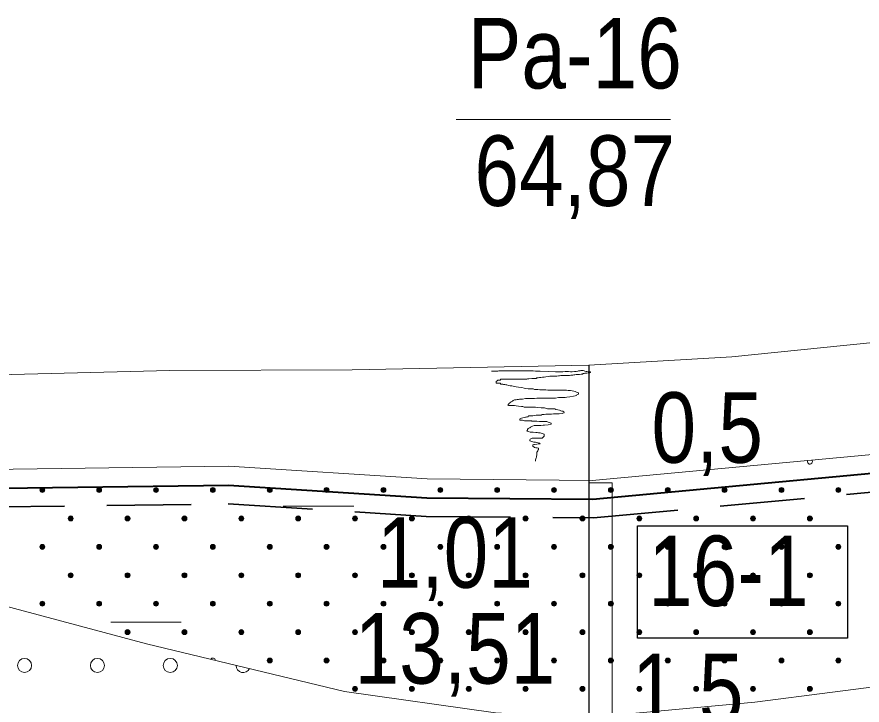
# Model space of a CAD drawing. Extents: x 640121 to 640955, y 6441885 to 6442246.
# Drawn here: x 640850.27 to 640886.22, y 6442146.39 to 6442175.68 of the extents above; entities that cross this region are included whole.
import ezdxf
from ezdxf.enums import TextEntityAlignment as Align

# ---------------------------------------------------------------- set-up
doc = ezdxf.new("R2010")
doc.units = 0
doc.header["$LTSCALE"] = 1.2
doc.linetypes.add('MEDIUM_DASHED', pattern=[4.5, 3, -1.5])
for name, color, linetype, lineweight in [('31', 7, 'Continuous', 13), ('32', 7, 'Continuous', 13), ('33', 7, 'Continuous', 13), ('35', 7, 'Continuous', 35), ('40', 7, 'Continuous', 13), ('43', 7, 'Continuous', 13), ('45', 7, 'Continuous', 13), ('47', 7, 'Continuous', 13)]:
    doc.layers.add(name, color=color, linetype=linetype, lineweight=lineweight)

msp = doc.modelspace()

# ---------------------------------------------------------------- hatches: boundary and pattern name
at = {"layer": '45'}
for points in [[(640851.424, 6442155.622, 1), (640851.275, 6442155.473, 1)], [(640853.842, 6442155.622, 1), (640853.694, 6442155.473, 1)], [(640856.26, 6442155.622, 1), (640856.112, 6442155.473, 1)], [(640858.679, 6442155.622, 1), (640858.53, 6442155.473, 1)], [(640861.097, 6442155.622, 1), (640860.949, 6442155.473, 1)], [(640863.515, 6442155.622, 1), (640863.367, 6442155.473, 1)], [(640865.934, 6442155.622, 1), (640865.785, 6442155.473, 1)], [(640868.352, 6442155.622, 1), (640868.203, 6442155.473, 1)], [(640870.77, 6442155.622, 1), (640870.622, 6442155.473, 1)], [(640873.189, 6442155.622, 1), (640873.04, 6442155.473, 1)], [(640875.607, 6442155.622, 1), (640875.458, 6442155.473, 1)], [(640878.025, 6442155.622, 1), (640877.877, 6442155.473, 1)], [(640880.443, 6442155.622, 1), (640880.295, 6442155.473, 1)], [(640882.862, 6442155.622, 1), (640882.713, 6442155.473, 1)], [(640885.28, 6442155.622, 1), (640885.132, 6442155.473, 1)], [(640852.633, 6442154.413, 1), (640852.484, 6442154.264, 1)], [(640855.051, 6442154.413, 1), (640854.903, 6442154.264, 1)], [(640857.47, 6442154.413, 1), (640857.321, 6442154.264, 1)], [(640859.888, 6442154.413, 1), (640859.739, 6442154.264, 1)], [(640862.306, 6442154.413, 1), (640862.158, 6442154.264, 1)], [(640864.724, 6442154.413, 1), (640864.576, 6442154.264, 1)], [(640867.143, 6442154.413, 1), (640866.994, 6442154.264, 1)], [(640869.561, 6442154.413, 1), (640869.413, 6442154.264, 1)], [(640871.979, 6442154.413, 1), (640871.831, 6442154.264, 1)], [(640874.398, 6442154.413, 1), (640874.249, 6442154.264, 1)], [(640876.816, 6442154.413, 1), (640876.667, 6442154.264, 1)], [(640879.234, 6442154.413, 1), (640879.086, 6442154.264, 1)], [(640881.653, 6442154.413, 1), (640881.504, 6442154.264, 1)], [(640884.071, 6442154.413, 1), (640883.922, 6442154.264, 1)], [(640851.424, 6442153.204, 1), (640851.275, 6442153.055, 1)], [(640853.842, 6442153.204, 1), (640853.694, 6442153.055, 1)], [(640856.26, 6442153.204, 1), (640856.112, 6442153.055, 1)], [(640858.679, 6442153.204, 1), (640858.53, 6442153.055, 1)], [(640861.097, 6442153.204, 1), (640860.949, 6442153.055, 1)], [(640863.515, 6442153.204, 1), (640863.367, 6442153.055, 1)], [(640865.934, 6442153.204, 1), (640865.785, 6442153.055, 1)], [(640868.352, 6442153.204, 1), (640868.203, 6442153.055, 1)], [(640870.77, 6442153.204, 1), (640870.622, 6442153.055, 1)], [(640873.189, 6442153.204, 1), (640873.04, 6442153.055, 1)], [(640875.607, 6442153.204, 1), (640875.458, 6442153.055, 1)], [(640878.025, 6442153.204, 1), (640877.877, 6442153.055, 1)], [(640880.443, 6442153.204, 1), (640880.295, 6442153.055, 1)], [(640882.862, 6442153.204, 1), (640882.713, 6442153.055, 1)], [(640885.28, 6442153.204, 1), (640885.132, 6442153.055, 1)], [(640852.633, 6442151.994, 1), (640852.484, 6442151.846, 1)], [(640855.051, 6442151.994, 1), (640854.903, 6442151.846, 1)], [(640857.47, 6442151.994, 1), (640857.321, 6442151.846, 1)], [(640859.888, 6442151.994, 1), (640859.739, 6442151.846, 1)], [(640862.306, 6442151.994, 1), (640862.158, 6442151.846, 1)], [(640864.724, 6442151.994, 1), (640864.576, 6442151.846, 1)], [(640867.143, 6442151.994, 1), (640866.994, 6442151.846, 1)], [(640869.561, 6442151.994, 1), (640869.413, 6442151.846, 1)], [(640871.979, 6442151.994, 1), (640871.831, 6442151.846, 1)], [(640874.398, 6442151.994, 1), (640874.249, 6442151.846, 1)], [(640876.816, 6442151.994, 1), (640876.667, 6442151.846, 1)], [(640879.234, 6442151.994, 1), (640879.086, 6442151.846, 1)], [(640881.653, 6442151.994, 1), (640881.504, 6442151.846, 1)], [(640884.071, 6442151.994, 1), (640883.922, 6442151.846, 1)], [(640851.424, 6442150.785, 1), (640851.275, 6442150.637, 1)], [(640853.842, 6442150.785, 1), (640853.694, 6442150.637, 1)], [(640856.26, 6442150.785, 1), (640856.112, 6442150.637, 1)], [(640858.679, 6442150.785, 1), (640858.53, 6442150.637, 1)], [(640861.097, 6442150.785, 1), (640860.949, 6442150.637, 1)], [(640863.515, 6442150.785, 1), (640863.367, 6442150.637, 1)], [(640865.934, 6442150.785, 1), (640865.785, 6442150.637, 1)], [(640868.352, 6442150.785, 1), (640868.203, 6442150.637, 1)], [(640870.77, 6442150.785, 1), (640870.622, 6442150.637, 1)], [(640873.189, 6442150.785, 1), (640873.04, 6442150.637, 1)], [(640875.607, 6442150.785, 1), (640875.458, 6442150.637, 1)], [(640878.025, 6442150.785, 1), (640877.877, 6442150.637, 1)], [(640880.443, 6442150.785, 1), (640880.295, 6442150.637, 1)], [(640882.862, 6442150.785, 1), (640882.713, 6442150.637, 1)], [(640885.28, 6442150.785, 1), (640885.132, 6442150.637, 1)], [(640855.051, 6442149.576, 1), (640854.903, 6442149.428, 1)], [(640857.47, 6442149.576, 1), (640857.321, 6442149.428, 1)], [(640859.888, 6442149.576, 1), (640859.739, 6442149.428, 1)], [(640862.306, 6442149.576, 1), (640862.158, 6442149.428, 1)], [(640864.724, 6442149.576, 1), (640864.576, 6442149.428, 1)], [(640867.143, 6442149.576, 1), (640866.994, 6442149.428, 1)], [(640869.561, 6442149.576, 1), (640869.413, 6442149.428, 1)], [(640871.979, 6442149.576, 1), (640871.831, 6442149.428, 1)], [(640874.398, 6442149.576, 1), (640874.249, 6442149.428, 1)], [(640876.816, 6442149.576, 1), (640876.667, 6442149.428, 1)], [(640879.234, 6442149.576, 1), (640879.086, 6442149.428, 1)], [(640881.653, 6442149.576, 1), (640881.504, 6442149.428, 1)], [(640884.071, 6442149.576, 1), (640883.922, 6442149.428, 1)], [(640861.097, 6442148.367, 1), (640860.949, 6442148.219, 1)], [(640863.515, 6442148.367, 1), (640863.367, 6442148.219, 1)], [(640865.934, 6442148.367, 1), (640865.785, 6442148.219, 1)], [(640868.352, 6442148.367, 1), (640868.203, 6442148.219, 1)], [(640870.77, 6442148.367, 1), (640870.622, 6442148.219, 1)], [(640873.189, 6442148.367, 1), (640873.04, 6442148.219, 1)], [(640875.607, 6442148.367, 1), (640875.458, 6442148.219, 1)], [(640878.025, 6442148.367, 1), (640877.877, 6442148.219, 1)], [(640880.443, 6442148.367, 1), (640880.295, 6442148.219, 1)], [(640882.862, 6442148.367, 1), (640882.713, 6442148.219, 1)], [(640885.28, 6442148.367, 1), (640885.132, 6442148.219, 1)], [(640864.724, 6442147.158, 1), (640864.576, 6442147.009, 1)], [(640867.143, 6442147.158, 1), (640866.994, 6442147.009, 1)], [(640869.561, 6442147.158, 1), (640869.413, 6442147.009, 1)], [(640871.979, 6442147.158, 1), (640871.831, 6442147.009, 1)], [(640874.398, 6442147.158, 1), (640874.249, 6442147.009, 1)], [(640876.816, 6442147.158, 1), (640876.667, 6442147.009, 1)], [(640879.234, 6442147.158, 1), (640879.086, 6442147.009, 1)], [(640881.653, 6442147.158, 1), (640881.504, 6442147.009, 1)], [(640884.071, 6442147.158, 1), (640883.922, 6442147.009, 1)]]:
    msp.add_hatch(color=256, dxfattribs=at).paths.add_polyline_path(points)

# ---------------------------------------------------------------- linework, layer by layer
at = {"layer": '31'}
for points in [[(640766.27, 6442166.81), (640772.42, 6442164.18), (640775.97, 6442162.88), (640778.51, 6442161.86), (640779.92, 6442161.1), (640782.4, 6442159.37), (640784.73, 6442157.26), (640785.79, 6442156.66), (640789.05, 6442156.34), (640792.15, 6442156.48), (640797.43, 6442156.68), (640805.3, 6442157.27), (640819.95, 6442158.83), (640830.66, 6442159.34), (640843.85, 6442160.31), (640856.77, 6442160.63), (640864.53, 6442160.67), (640874.59, 6442160.86), (640880.68, 6442161.21), (640890.6, 6442162.23)], [(640771.49, 6442163.12), (640774.28, 6442161.82), (640776.71, 6442160.81), (640779.36, 6442159.25), (640784.92, 6442155.11), (640785.41, 6442154.87), (640785.78, 6442154.67), (640787.15, 6442154.55), (640789.13, 6442154.57), (640793.8, 6442154.85), (640797.19, 6442155.11), (640800.45, 6442155.32), (640807.52, 6442155.7), (640815.1, 6442156.02), (640823.55, 6442156.02), (640837.86, 6442156.27), (640859.29, 6442156.56), (640867.72, 6442156.02), (640874.73, 6442155.96), (640892.32, 6442157.59), (640908.53, 6442160.16), (640920.53, 6442162.05), (640928.43, 6442163.08), (640933.07, 6442163.64)], [(640827.29, 6442156.09), (640846.55, 6442151.47), (640855.78, 6442149), (640864.21, 6442146.97), (640870.63, 6442146.07), (640874.45, 6442145.85), (640881.65, 6442146.52), (640888.26, 6442147.37), (640905.62, 6442150.12), (640920.7, 6442152.04), (640935.32, 6442154.62)]]:
    msp.add_lwpolyline(points, dxfattribs=at)
at = {"layer": '32'}
msp.add_line((640868.95, 6442171.32), (640878.07, 6442171.32), dxfattribs=at)
at = {"layer": '32', "lineweight": 25}
msp.add_line((640874.59, 6442160.86), (640874.59, 6442115.86), dxfattribs=at)
at = {"layer": '33'}
msp.add_lwpolyline([(640875.59, 6442145.96), (640875.59, 6442155.86), (640874.73, 6442155.86), (640874.59, 6442155.86), (640874.59, 6442145.86), (640874.63, 6442145.86)], close=True, dxfattribs=at)
at = {"layer": '33', "lineweight": 25}
msp.add_lwpolyline([(640876.67, 6442154.03), (640885.59, 6442154.03), (640885.59, 6442149.25), (640876.67, 6442149.25)], close=True, dxfattribs=at)
at = {"layer": '35', "lineweight": 40}
msp.add_lwpolyline([(640771.15, 6442162.4), (640773.96, 6442161.09), (640776.35, 6442160.1), (640778.91, 6442158.58), (640784.51, 6442154.42), (640785.04, 6442154.16), (640785.54, 6442153.88), (640787.12, 6442153.75), (640789.16, 6442153.77), (640793.85, 6442154.05), (640797.24, 6442154.31), (640800.5, 6442154.52), (640807.56, 6442154.9), (640815.12, 6442155.22), (640823.56, 6442155.22), (640837.88, 6442155.47), (640859.27, 6442155.76), (640867.7, 6442155.22), (640874.77, 6442155.16), (640892.41, 6442156.8), (640908.65, 6442159.37), (640919.89, 6442161.14)], dxfattribs=at)
at = {"layer": '35', "linetype": 'MEDIUM_DASHED'}
msp.add_lwpolyline([(640770.82, 6442161.67), (640773.64, 6442160.36), (640775.99, 6442159.38), (640778.47, 6442157.91), (640784.09, 6442153.73), (640784.67, 6442153.45), (640785.3, 6442153.1), (640787.09, 6442152.95), (640789.18, 6442152.97), (640793.9, 6442153.25), (640797.3, 6442153.51), (640800.54, 6442153.72), (640807.6, 6442154.1), (640815.14, 6442154.42), (640823.57, 6442154.42), (640837.89, 6442154.67), (640859.25, 6442154.96), (640867.67, 6442154.42), (640874.8, 6442154.36), (640892.51, 6442156), (640908.78, 6442158.58), (640919.09, 6442160.21)], dxfattribs=at)
at = {"layer": '40'}
for points in [[(640870.46, 6442160.6), (640870.52, 6442160.6), (640870.63, 6442160.6), (640870.73, 6442160.6), (640870.76, 6442160.62), (640870.87, 6442160.62), (640871.02, 6442160.62), (640871.35, 6442160.62), (640871.53, 6442160.62), (640871.56, 6442160.62), (640871.6, 6442160.62), (640871.67, 6442160.62), (640871.75, 6442160.62), (640871.86, 6442160.62), (640871.95, 6442160.62), (640872.01, 6442160.62), (640872.09, 6442160.62), (640872.16, 6442160.62), (640872.23, 6442160.62), (640872.32, 6442160.6), (640872.37, 6442160.6), (640872.44, 6442160.6), (640872.53, 6442160.6), (640872.87, 6442160.59), (640873.18, 6442160.58), (640873.28, 6442160.58), (640873.34, 6442160.58), (640873.37, 6442160.58), (640873.42, 6442160.58), (640873.49, 6442160.58), (640873.59, 6442160.59), (640873.64, 6442160.59), (640873.67, 6442160.59), (640873.7, 6442160.59), (640873.73, 6442160.59), (640873.81, 6442160.58), (640873.84, 6442160.58), (640873.89, 6442160.58), (640873.99, 6442160.59), (640874.05, 6442160.59), (640874.12, 6442160.6), (640874.15, 6442160.62), (640874.23, 6442160.62), (640874.26, 6442160.63), (640874.31, 6442160.63), (640874.36, 6442160.63), (640874.39, 6442160.62), (640874.43, 6442160.6), (640874.48, 6442160.59), (640874.51, 6442160.59)], [(640871.99, 6442160.28), (640871.96, 6442160.27), (640871.9, 6442160.27), (640871.86, 6442160.26), (640871.83, 6442160.26), (640871.79, 6442160.26), (640871.74, 6442160.26), (640871.69, 6442160.26), (640871.65, 6442160.26), (640871.57, 6442160.26), (640871.54, 6442160.26), (640871.48, 6442160.27), (640871.44, 6442160.27), (640871.41, 6442160.27), (640871.37, 6442160.27), (640871.32, 6442160.27), (640871.27, 6442160.27), (640871.2, 6442160.27), (640871.17, 6442160.27), (640871.13, 6442160.27), (640871.07, 6442160.27), (640871.03, 6442160.27), (640870.99, 6442160.27), (640870.95, 6442160.27), (640870.9, 6442160.27), (640870.85, 6442160.26), (640870.82, 6442160.23), (640870.77, 6442160.23), (640870.73, 6442160.22), (640870.71, 6442160.21), (640870.69, 6442160.2), (640870.66, 6442160.17), (640870.65, 6442160.14), (640870.66, 6442160.1), (640870.76, 6442160.09), (640870.82, 6442160.09), (640870.85, 6442160.06), (640870.9, 6442160.06), (640870.94, 6442160.05), (640870.96, 6442160.04), (640871.02, 6442160.04), (640871.07, 6442160.03), (640871.11, 6442160.02), (640871.18, 6442159.99), (640871.25, 6442159.98), (640871.32, 6442159.98), (640871.37, 6442159.97), (640871.42, 6442159.96), (640871.5, 6442159.94), (640871.61, 6442159.93)], [(640874.51, 6442160.59), (640874.56, 6442160.58), (640874.6, 6442160.58), (640874.65, 6442160.58), (640874.67, 6442160.56), (640874.65, 6442160.54), (640874.66, 6442160.56), (640874.62, 6442160.54), (640874.57, 6442160.53), (640874.51, 6442160.52), (640874.48, 6442160.52), (640874.43, 6442160.52), (640874.39, 6442160.51), (640874.36, 6442160.51), (640874.33, 6442160.48), (640874.27, 6442160.48), (640874.2, 6442160.47), (640874.17, 6442160.47), (640874.05, 6442160.46), (640874, 6442160.45), (640873.96, 6442160.45), (640873.91, 6442160.44), (640873.87, 6442160.44), (640873.83, 6442160.44), (640873.77, 6442160.42), (640873.73, 6442160.42), (640873.63, 6442160.42), (640873.57, 6442160.42), (640873.49, 6442160.42), (640873.41, 6442160.42), (640873.35, 6442160.41), (640873.3, 6442160.41), (640873.24, 6442160.4), (640873.18, 6442160.4), (640873.01, 6442160.4), (640872.98, 6442160.4), (640872.94, 6442160.39), (640872.87, 6442160.38), (640872.77, 6442160.36), (640872.69, 6442160.35), (640872.63, 6442160.35), (640872.55, 6442160.34), (640872.49, 6442160.34), (640872.44, 6442160.32), (640872.38, 6442160.32), (640872.35, 6442160.3), (640872.32, 6442160.3), (640872.26, 6442160.3), (640872.21, 6442160.29), (640872.17, 6442160.29), (640872.04, 6442160.28), (640871.99, 6442160.28)], [(640871.61, 6442159.93), (640871.75, 6442159.91), (640871.85, 6442159.88), (640871.91, 6442159.87), (640872.01, 6442159.86), (640872.1, 6442159.86), (640872.17, 6442159.85), (640872.23, 6442159.85), (640872.28, 6442159.82), (640872.37, 6442159.82), (640872.43, 6442159.82), (640872.51, 6442159.81), (640872.59, 6442159.81), (640872.67, 6442159.81), (640872.76, 6442159.81), (640872.85, 6442159.8), (640872.91, 6442159.8), (640872.94, 6442159.8), (640873.01, 6442159.8), (640873.09, 6442159.8), (640873.17, 6442159.8), (640873.27, 6442159.8), (640873.35, 6442159.8), (640873.41, 6442159.8), (640873.49, 6442159.8), (640873.53, 6442159.8), (640873.59, 6442159.8), (640873.65, 6442159.8), (640873.71, 6442159.79), (640873.77, 6442159.79), (640873.82, 6442159.78), (640873.95, 6442159.76), (640874.01, 6442159.74), (640874.07, 6442159.72), (640874.12, 6442159.7), (640874.15, 6442159.69), (640874.15, 6442159.66), (640874.14, 6442159.62), (640874.12, 6442159.61), (640874.09, 6442159.6), (640874.07, 6442159.57), (640874.02, 6442159.56), (640873.94, 6442159.54), (640873.79, 6442159.52), (640873.66, 6442159.5), (640873.59, 6442159.49), (640873.49, 6442159.49), (640873.41, 6442159.48), (640873.31, 6442159.48), (640873.18, 6442159.46), (640872.99, 6442159.46), (640872.82, 6442159.46)], [(640872.82, 6442159.46), (640872.74, 6442159.46), (640872.67, 6442159.46), (640872.58, 6442159.46), (640872.52, 6442159.46), (640872.46, 6442159.46), (640872.38, 6442159.46), (640872.29, 6442159.45), (640872.11, 6442159.45), (640872.03, 6442159.45), (640871.98, 6442159.44), (640871.9, 6442159.44), (640871.78, 6442159.42), (640871.65, 6442159.42), (640871.6, 6442159.4), (640871.54, 6442159.4), (640871.51, 6442159.39), (640871.48, 6442159.38), (640871.44, 6442159.38), (640871.41, 6442159.37), (640871.37, 6442159.36), (640871.35, 6442159.33), (640871.29, 6442159.3), (640871.25, 6442159.27), (640871.24, 6442159.25), (640871.2, 6442159.24), (640871.19, 6442159.21), (640871.17, 6442159.19), (640871.15, 6442159.16), (640871.18, 6442159.15), (640871.21, 6442159.15), (640871.27, 6442159.15), (640871.32, 6442159.15), (640871.43, 6442159.14), (640871.51, 6442159.13), (640871.61, 6442159.12), (640871.73, 6442159.1), (640871.79, 6442159.1), (640871.85, 6442159.08), (640871.91, 6442159.08), (640872.08, 6442159.08), (640872.21, 6442159.08), (640872.32, 6442159.07), (640872.43, 6442159.06), (640872.57, 6442159.04), (640872.71, 6442159.04), (640872.83, 6442159.01), (640872.92, 6442159.01), (640873.01, 6442159.01), (640873.1, 6442159)], [(640873.1, 6442159), (640873.15, 6442159), (640873.19, 6442158.98), (640873.28, 6442158.96), (640873.35, 6442158.95), (640873.4, 6442158.92), (640873.45, 6442158.91), (640873.51, 6442158.9), (640873.53, 6442158.89), (640873.54, 6442158.84), (640873.52, 6442158.83), (640873.49, 6442158.82), (640873.46, 6442158.8), (640873.34, 6442158.79), (640873.28, 6442158.79), (640873.24, 6442158.79), (640873.17, 6442158.79), (640873.09, 6442158.79), (640873, 6442158.78), (640872.95, 6442158.78), (640872.91, 6442158.78), (640872.77, 6442158.78), (640872.7, 6442158.76), (640872.67, 6442158.76), (640872.61, 6442158.76), (640872.57, 6442158.74), (640872.51, 6442158.74), (640872.43, 6442158.74), (640872.35, 6442158.73), (640872.27, 6442158.72), (640872.21, 6442158.71), (640872.17, 6442158.71), (640872.13, 6442158.71), (640872.09, 6442158.7), (640872.03, 6442158.7), (640872.02, 6442158.67), (640871.96, 6442158.66), (640871.93, 6442158.65), (640871.9, 6442158.65), (640871.85, 6442158.64), (640871.79, 6442158.62), (640871.73, 6442158.61), (640871.68, 6442158.59), (640871.66, 6442158.56), (640871.66, 6442158.52), (640871.69, 6442158.52), (640871.77, 6442158.52), (640871.86, 6442158.5), (640871.95, 6442158.5), (640871.99, 6442158.5), (640872.09, 6442158.49), (640872.15, 6442158.49)], [(640872.15, 6442158.49), (640872.17, 6442158.48), (640872.21, 6442158.48), (640872.27, 6442158.48), (640872.34, 6442158.48), (640872.38, 6442158.48), (640872.49, 6442158.47), (640872.57, 6442158.47), (640872.61, 6442158.47), (640872.65, 6442158.47), (640872.69, 6442158.47), (640872.75, 6442158.47), (640872.81, 6442158.46), (640872.86, 6442158.43), (640872.91, 6442158.42), (640872.95, 6442158.41), (640872.99, 6442158.4), (640872.99, 6442158.35), (640872.87, 6442158.32), (640872.71, 6442158.31), (640872.65, 6442158.31), (640872.55, 6442158.3), (640872.49, 6442158.3), (640872.41, 6442158.3), (640872.34, 6442158.29), (640872.27, 6442158.29), (640872.2, 6442158.26), (640872.11, 6442158.23), (640872.09, 6442158.2), (640872.04, 6442158.18), (640872.02, 6442158.16), (640871.99, 6442158.13), (640871.98, 6442158.1), (640871.96, 6442158.06), (640871.98, 6442158.05), (640872.03, 6442158.04), (640872.1, 6442158.01), (640872.23, 6442158.01), (640872.34, 6442158), (640872.4, 6442157.99), (640872.45, 6442157.98), (640872.52, 6442157.98), (640872.61, 6442157.96), (640872.7, 6442157.93), (640872.7, 6442157.88), (640872.69, 6442157.84), (640872.68, 6442157.82), (640872.61, 6442157.76), (640872.57, 6442157.75), (640872.51, 6442157.75), (640872.43, 6442157.75), (640872.34, 6442157.75), (640872.27, 6442157.75), (640872.19, 6442157.75), (640872.1, 6442157.72), (640872.09, 6442157.69), (640872.08, 6442157.66), (640872.09, 6442157.64), (640872.13, 6442157.63), (640872.25, 6442157.59), (640872.33, 6442157.58), (640872.38, 6442157.57), (640872.44, 6442157.56), (640872.5, 6442157.54), (640872.53, 6442157.52), (640872.51, 6442157.51), (640872.45, 6442157.51), (640872.38, 6442157.5), (640872.28, 6442157.48), (640872.25, 6442157.48), (640872.21, 6442157.47), (640872.21, 6442157.42), (640872.23, 6442157.4), (640872.26, 6442157.39), (640872.29, 6442157.36), (640872.34, 6442157.35), (640872.4, 6442157.34), (640872.45, 6442157.33), (640872.46, 6442157.28), (640872.44, 6442157.26), (640872.43, 6442157.22), (640872.4, 6442157.18), (640872.38, 6442157.16), (640872.38, 6442157.11), (640872.38, 6442157.06), (640872.38, 6442157.03), (640872.37, 6442156.99), (640872.37, 6442156.94), (640872.35, 6442156.92), (640872.34, 6442156.87), (640872.33, 6442156.84), (640872.33, 6442156.79), (640872.33, 6442156.78), (640872.33, 6442156.81)]]:
    msp.add_lwpolyline(points, dxfattribs=at)
at = {"layer": '43'}
for centre in [(640850.594, 6442148.081), (640853.694, 6442148.081), (640856.794, 6442148.081)]:
    msp.add_circle(centre, 0.3, dxfattribs=at)
msp.add_arc((640859.894, 6442148.081), 0.3, 179.7452, 333.2633, dxfattribs=at)
at = {"layer": '45'}
for centre in [(640851.35, 6442155.548), (640853.768, 6442155.548), (640856.186, 6442155.548), (640858.604, 6442155.548), (640861.023, 6442155.548), (640863.441, 6442155.548), (640865.859, 6442155.548), (640868.278, 6442155.548), (640870.696, 6442155.548), (640873.114, 6442155.548), (640875.533, 6442155.548), (640877.951, 6442155.548), (640880.369, 6442155.548), (640882.788, 6442155.548), (640885.206, 6442155.548), (640852.559, 6442154.339), (640854.977, 6442154.339), (640857.395, 6442154.339), (640859.814, 6442154.339), (640862.232, 6442154.339), (640864.65, 6442154.339), (640867.069, 6442154.339), (640869.487, 6442154.339), (640871.905, 6442154.339), (640874.323, 6442154.339), (640876.742, 6442154.339), (640879.16, 6442154.339), (640881.578, 6442154.339), (640883.997, 6442154.339), (640851.35, 6442153.129), (640853.768, 6442153.129), (640856.186, 6442153.129), (640858.604, 6442153.129), (640861.023, 6442153.129), (640863.441, 6442153.129), (640865.859, 6442153.129), (640868.278, 6442153.129), (640870.696, 6442153.129), (640873.114, 6442153.129), (640875.533, 6442153.129), (640877.951, 6442153.129), (640880.369, 6442153.129), (640882.788, 6442153.129), (640885.206, 6442153.129), (640852.559, 6442151.92), (640854.977, 6442151.92), (640857.395, 6442151.92), (640859.814, 6442151.92), (640862.232, 6442151.92), (640864.65, 6442151.92), (640867.069, 6442151.92), (640869.487, 6442151.92), (640871.905, 6442151.92), (640874.323, 6442151.92), (640876.742, 6442151.92), (640879.16, 6442151.92), (640881.578, 6442151.92), (640883.997, 6442151.92), (640851.35, 6442150.711), (640853.768, 6442150.711), (640856.186, 6442150.711), (640858.604, 6442150.711), (640861.023, 6442150.711), (640863.441, 6442150.711), (640865.859, 6442150.711), (640868.278, 6442150.711), (640870.696, 6442150.711), (640873.114, 6442150.711), (640875.533, 6442150.711), (640877.951, 6442150.711), (640880.369, 6442150.711), (640882.788, 6442150.711), (640885.206, 6442150.711), (640854.977, 6442149.502), (640857.395, 6442149.502), (640859.814, 6442149.502), (640862.232, 6442149.502), (640864.65, 6442149.502), (640867.069, 6442149.502), (640869.487, 6442149.502), (640871.905, 6442149.502), (640874.323, 6442149.502), (640876.742, 6442149.502), (640879.16, 6442149.502), (640881.578, 6442149.502), (640883.997, 6442149.502), (640861.023, 6442148.293), (640863.441, 6442148.293), (640865.859, 6442148.293), (640868.278, 6442148.293), (640870.696, 6442148.293), (640873.114, 6442148.293), (640875.533, 6442148.293), (640877.951, 6442148.293), (640880.369, 6442148.293), (640882.788, 6442148.293), (640885.206, 6442148.293), (640864.65, 6442147.084), (640867.069, 6442147.084), (640869.487, 6442147.084), (640871.905, 6442147.084), (640874.323, 6442147.084), (640876.742, 6442147.084), (640879.16, 6442147.084), (640881.578, 6442147.084), (640883.997, 6442147.084)]:
    msp.add_circle(centre, 0.105, dxfattribs=at)
for centre, start, end in [((640883.997, 6442156.757), 148.1876, 42.4028), ((640858.604, 6442148.293), 0.9361, 152.0725)]:
    msp.add_arc(centre, 0.105, start, end, dxfattribs=at)
at = {"layer": '47'}
for p, q in [((640861.6, 6442154.86), (640864.6, 6442154.86)), ((640854.26, 6442149.93), (640857.26, 6442149.93))]:
    msp.add_line(p, q, dxfattribs=at)

# ---------------------------------------------------------------- texts
at = {"layer": '32', "width": 0.85}
for s, p in [('Pa-16', (640874, 6442172.64)), ('64,87', (640873.995, 6442167.64)), ('0,5', (640879.63, 6442156.71)), ('1,01', (640868.895, 6442151.39)), ('1,5', (640878.8, 6442145.59))]:
    msp.add_text(s, height=3, dxfattribs=at).set_placement(p, align=Align.CENTER)
at = {"layer": '33', "width": 0.85}
for s, p in [('16-1', (640880.53, 6442150.61)), ('13,51', (640868.9, 6442147.31))]:
    msp.add_text(s, height=3, dxfattribs=at).set_placement(p, align=Align.CENTER)

doc.saveas('drawing.dxf')
